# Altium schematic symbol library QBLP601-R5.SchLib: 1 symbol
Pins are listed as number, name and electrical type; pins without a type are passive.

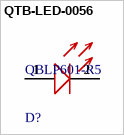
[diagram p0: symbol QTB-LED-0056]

## QTB-LED-0056
designator D?, comment QBLP601-R5
LED RED CLEAR 0603 SMD; Manufacturer: QT Brightek (QTB); Lens Size: 0.8mm; Luminous Intensity: 27mcd; Test Current: 5mA; Lens Color: Colorless; Lens Style: Flat; Forward Voltage: 1.8V; Wavelength - Dominant: 625nm
footprint QBLP601-R35-MFG
pins: 1 ANODE (+), 2 CATHODE (-)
